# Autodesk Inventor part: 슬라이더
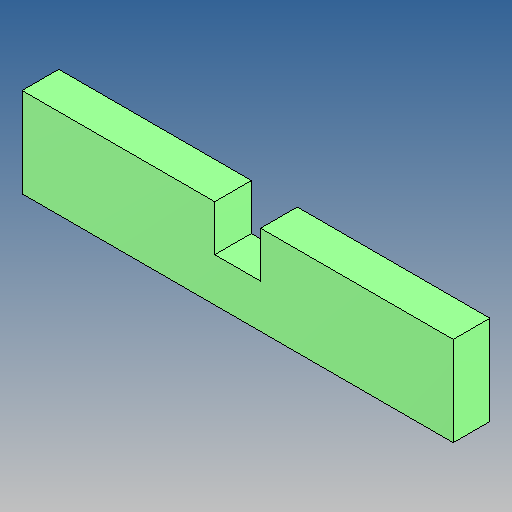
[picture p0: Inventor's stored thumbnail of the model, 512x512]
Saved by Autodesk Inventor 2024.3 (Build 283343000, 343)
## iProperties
Created: 2025-06
Part Number: 슬라이더
Material: 강철, 합금
Document SubType Name: Modeling
Designer: user
Density: 7.73 g/cm^3
Appearance: 기본값
Author: jhkim
Sending System: Autodesk Inventor 2026
Preprocessor: ST-DEVELOPER v20.1
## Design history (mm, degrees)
node "슬라이더1"
node "솔리드2"
node "솔리드1"
